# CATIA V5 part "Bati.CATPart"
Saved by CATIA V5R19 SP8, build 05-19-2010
Part number: Bati
Publications: "entraxe", "rc", "ra", "L", "H", "a"
Bounding box of the stored display mesh (mm): x -105 to 95, y -20 to 20, z -310 to 20
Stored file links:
  C:\Users\ThinkMotion\Desktop\EU_thinkMotion\iao\IAO_MMS_Groupe3\evulliez\evulliez\evulliez\Mecanisme\Bati.CATPart
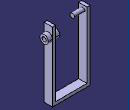
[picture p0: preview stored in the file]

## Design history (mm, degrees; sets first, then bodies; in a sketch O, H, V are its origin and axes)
Parameters
  entraxe = 30 mm
  rc = 10 mm
  ra = 10 mm
  L = 90 mm
  H = 330 mm
  a = 60 mm
Body1 (main body)
  Point1: (0, 0, 0)
  Line1: type PtDir, RefPoint Point1, Direction (1, 0, 0), Start -90, End 90 {= L}
  Line2: type PtDir, RefPoint Point1, Direction (0, 0, 1), Start -30 {= -entraxe}, End 0
  Line3: type PtDir, RefPoint vertex of Line2, Direction (1, 0, 0), Start -60, End 60 {= a}
  Plane1: type Normal, Curve Line1, RefPoint vertex of Line1
  Sketch1 on Plane1, origin (-90, 0, 0), H (0, 1, 0), V (0, 0, 1)
    circle A1 centre (0, 0) radius 10
    point P1 (0, 0)
    reference projected point E1 (0, 0) from Point1
    radius A1 = 10 {= rc}
    coincidence: E1 P1
  Pad1: profile Sketch1, direction (1, 0, 0), length 50 {= 5*rc}
  Sketch2 on Plane1, origin (-90, 0, 0), H (0, 1, 0), V (0, 0, 1)
    line L1 (-20, 20) -> (20, 20)
    line L2 (20, 20) -> (20, -310)
    line L3 (20, -310) -> (-20, -310)
    line L4 (-20, -310) -> (-20, 20)
    reference projected line E1 (0, -30) -> (0, 0) from Line2
    length L1 = 40 {= (rc +10mm)*2}
    distance E1 L2 = 20 {= rc +10mm}
    distance H L1 = 20 {= rc +10mm}
    length L2 = 330 {= H}
    horizontal: L1 H, L3 H
    vertical: L2 V, L4 V
  Pad2: profile Sketch2, direction (-1, 0, 0), length 15
  Plane2: type Normal, Curve Line3, RefPoint vertex of Line3
  Sketch3 on Plane2, origin (60, 0, 0), H (0, 1, 0), V (0, 0, 1)
    circle A1 centre (0, -30) radius 20
    point P1 (0, -30)
    reference projected point E1 (0, -30) from vertex of Line2
    radius A1 = 20 {= ra +10mm}
    coincidence: E1 P1
  Pad3: profile Sketch3, direction (-1, 0, 0), length 20 {= 2*ra}
  Sketch4 on Plane2, origin (60, 0, 0), H (0, 1, 0), V (0, 0, 1)
    line L1 (-20, 20) -> (20, 20)
    line L2 (20, 20) -> (20, -310)
    line L3 (20, -310) -> (-20, -310)
    line L4 (-20, -310) -> (-20, 20)
    distance V L2 = 20 {= rc +10mm}
    length L1 = 40 {= 2*(rc +10mm)}
    distance H L1 = 20 {= rc +10mm}
    length L2 = 330 {= H}
    horizontal: L1 H, L3 H
    vertical: L2 V, L4 V
  Pad4: profile Sketch4, direction (1, 0, 0), length 15
  Sketch5 on end face of Pad4, origin (75, 0, 0), H (0, 1, 0), V (0, 0, 1)
    circle A1 centre (0, -30) radius 20
    point P1 (0, -30)
    reference projected point E1 (0, -30) from vertex of Line2
    radius A1 = 20 {= ra +10mm}
    coincidence: P1 E1
  Pad5: profile Sketch5, direction (1, 0, 0), length 20 {= ra *2}
  Sketch6 on end face of Pad5, origin (95, 0, -30), H (0, 1, 0), V (0, 0, 1)
    point P1 (0, 0)
    reference projected point E1 (0, 0) from vertex of Line3
    coincidence: E1 P1
  Hole1: placed by Sketch6, at (95, 0, -30) direction (-1, 0, 0), diameter 20 {= ra *2}, through (limit type 6)
  Sketch7 on start face of Pad2, origin (-90, 0, 0), H (0, 1, 0), V (0, 0, 1)
    line L1 (-20, -310) -> (20, -310)
    line L2 (20, -310) -> (20, -295)
    line L3 (20, -295) -> (-20, -295)
    line L4 (-20, -295) -> (-20, -310)
    distance H L1 = 310 {= H -10mm-rc}
    length L1 = 40 {= (rc +10mm)*2}
    distance V L4 = 20 {= rc +10mm}
    length L4 = 15
    horizontal: L1 H, L3 H
    vertical: L2 V, L4 V
  Pad6: profile Sketch7, direction (1, 0, 0), up to start face of Pad4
